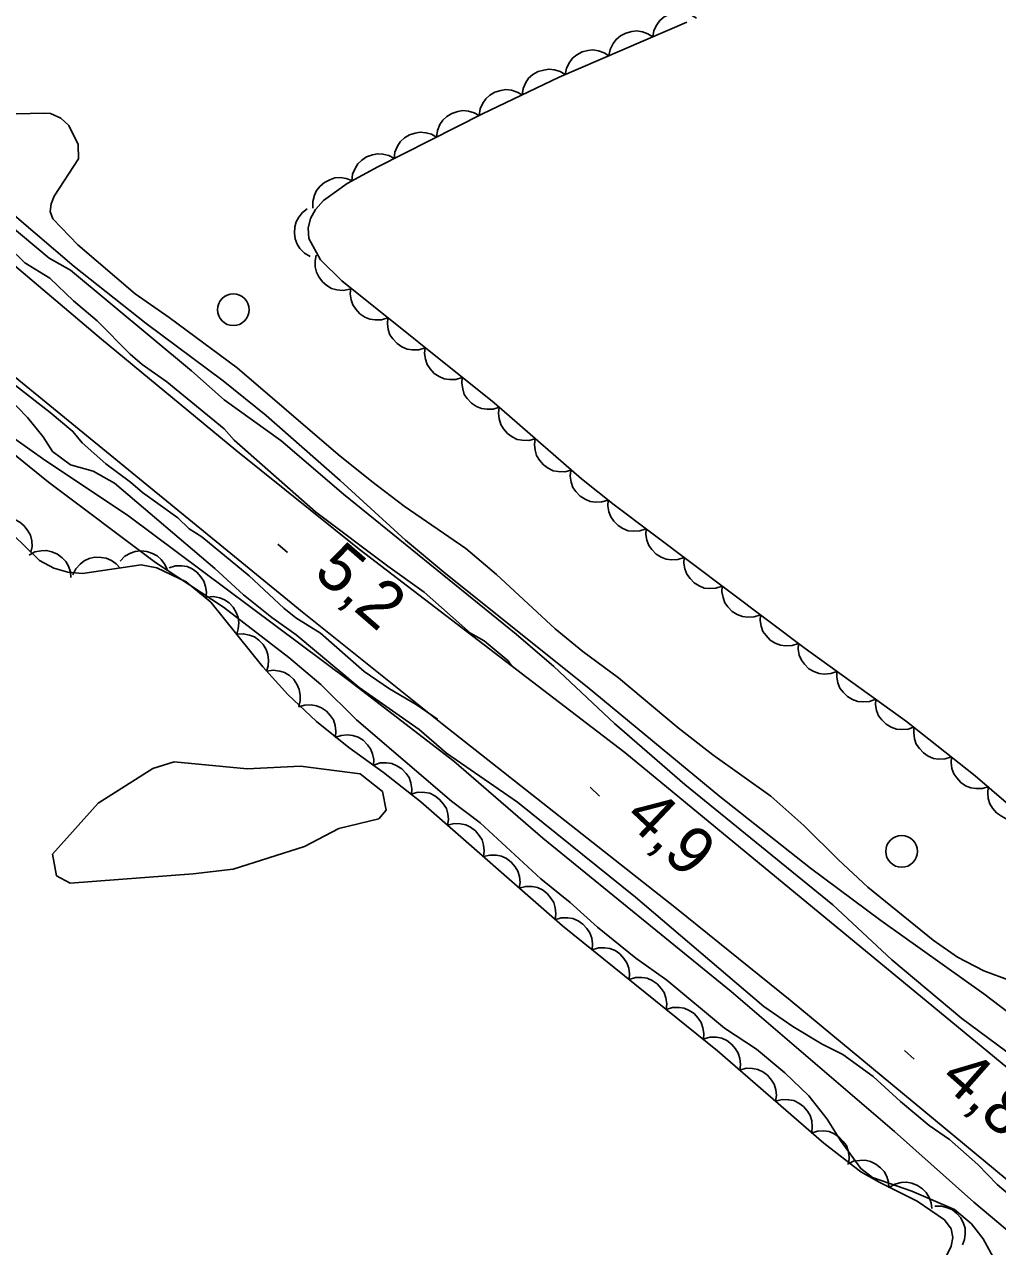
# Model space of a CAD drawing. Extents: x 336540 to 340074, y 5572036 to 5573747.
# Drawn here: x 337589.4 to 337650.7, y 5572818.2 to 5572895.2 of the extents above; entities that cross this region are included whole.
import ezdxf

# ---------------------------------------------------------------- set-up
doc = ezdxf.new("R2010")
doc.units = 0
for name, color, linetype in [('Niveau 1', 7, 'Continuous'), ('Niveau 19', 7, 'Continuous'), ('Niveau 2', 7, 'Continuous'), ('Niveau 3', 7, 'Continuous'), ('Niveau 36', 7, 'Continuous'), ('Niveau 4', 7, 'Continuous'), ('Niveau 44', 7, 'Continuous')]:
    doc.layers.add(name, color=color, linetype=linetype)

msp = doc.modelspace()

# ---------------------------------------------------------------- linework, layer by layer
at = {"layer": 'Niveau 1'}
for points in [[(337586.33, 5572883.16), (337589.41, 5572880.15), (337590.98, 5572879.19), (337592.48, 5572877.76), (337593.97, 5572876.5), (337596.05, 5572874.4), (337596.8, 5572873.74), (337598.35, 5572872.65), (337601.97, 5572869.7), (337602.6, 5572868.98), (337607.72, 5572864.48), (337612.26, 5572861.04), (337614.55, 5572859.4), (337617.48, 5572856.82), (337618.34, 5572856.34), (337619.84, 5572855.08), (337620.08, 5572854.75)], [(337615.4, 5572851.4), (337614.04, 5572852.34), (337612.38, 5572853.32), (337610.78, 5572854.41), (337608.02, 5572856.82), (337606.47, 5572857.8), (337605.72, 5572858.4), (337603.54, 5572860.43), (337600.55, 5572862.9), (337599.75, 5572863.39), (337599.05, 5572864.1), (337596.82, 5572865.68), (337596.07, 5572866.34), (337594.52, 5572867.49), (337593.02, 5572868.81), (337592.44, 5572869.53), (337591.01, 5572870.73), (337588.83, 5572872.43)], [(337600.02, 5572841.67), (337592.27, 5572841.09), (337591.4, 5572841.55), (337591.15, 5572842.9), (337594.03, 5572846.12), (337597.47, 5572848.31), (337598.81, 5572848.72), (337603.41, 5572848.28), (337606.77, 5572848.45), (337610.52, 5572847.96), (337611.92, 5572846.85), (337612.16, 5572845.67), (337611.69, 5572845.14), (337609.18, 5572844.52), (337607.03, 5572843.38), (337602.53, 5572841.96), (337600.02, 5572841.67)]]:
    msp.add_lwpolyline(points, dxfattribs=at)
at = {"layer": 'Niveau 19'}
for points in [[(337747.9, 5572743.42), (337733.2, 5572755.24), (337714.79, 5572770.78), (337697.31, 5572784.55), (337659.54, 5572815.53), (337637.6, 5572833.7), (337630.44, 5572839.48), (337615.68, 5572851.12), (337606.88, 5572858.17), (337562.43, 5572894.51)], [(337585.33, 5572882.89), (337594.24, 5572875.34), (337602.7, 5572868.36), (337610.46, 5572862.12), (337627.18, 5572849.32), (337671.83, 5572812.51), (337696.95, 5572792.34), (337706.42, 5572784.95), (337712.98, 5572779.69), (337742.53, 5572755.28)]]:
    msp.add_lwpolyline(points, dxfattribs=at)
at = {"layer": 'Niveau 2'}
for points in [[(337586.16, 5572889.48), (337590.66, 5572889.59), (337591.03, 5572889.55), (337591.69, 5572889.27), (337592.19, 5572888.81), (337592.78, 5572887.6), (337592.8, 5572886.7), (337591.27, 5572884.36), (337591.07, 5572883.87), (337591, 5572883.38), (337591.17, 5572882.92), (337592.74, 5572881.28), (337596.35, 5572878.21), (337598.5, 5572876.72), (337602.78, 5572873.54), (337609.13, 5572868.08), (337611.25, 5572866.37), (337613.3, 5572864.83), (337617.17, 5572862.16), (337619.1, 5572860.52), (337622.8, 5572857.11), (337624.54, 5572855.67), (337626.78, 5572854.02), (337630.55, 5572850.86), (337632.72, 5572849.16), (337636.38, 5572846.57), (337638.46, 5572844.72), (337640.63, 5572842.54), (337642.48, 5572840.83), (337646.6, 5572837.48), (337648.13, 5572836.42), (337649.79, 5572835.55), (337651.49, 5572834.93)], [(337667.74, 5572817.19), (337666.07, 5572818.77), (337665.04, 5572819.91), (337663.29, 5572821.4), (337661.2, 5572822.91), (337659.35, 5572824.37), (337654.91, 5572827.58), (337652.86, 5572829.25), (337648.4, 5572832.55), (337643.99, 5572836.26), (337640.29, 5572839.72), (337630.97, 5572847.29), (337626.53, 5572851.14), (337622.71, 5572854.73), (337620.34, 5572856.76), (337609.48, 5572865.58), (337605.52, 5572868.96), (337601.96, 5572871.53), (337599.9, 5572873.35), (337592.29, 5572879.69), (337590.94, 5572880.45), (337587.44, 5572883.37)], [(337588.34, 5572871.69), (337589.59, 5572870.41), (337590.57, 5572869.2), (337591.16, 5572868.26), (337592.29, 5572867.44), (337593.71, 5572867.03), (337595.05, 5572866.28), (337601.38, 5572860.9), (337603.17, 5572859.24), (337604.96, 5572857.81), (337606.5, 5572856.73), (337610.47, 5572853.4), (337614.23, 5572850.75), (337615.95, 5572849.27)], [(337650.49, 5572817.29), (337649.74, 5572818.67), (337649, 5572819.62), (337647.94, 5572820.53), (337645.25, 5572821.67), (337642.77, 5572822.53), (337642.04, 5572823.1), (337640.76, 5572824.88), (337639.93, 5572826.21), (337638.76, 5572827.69), (337637.25, 5572829.14), (337635.48, 5572830.63), (337633.46, 5572831.94), (337629.82, 5572834.97), (337627.88, 5572836.35), (337625.47, 5572838.31), (337623.74, 5572839.86), (337621.9, 5572841.36), (337618.08, 5572844.88), (337616.27, 5572846.24), (337610.29, 5572851.36), (337608.04, 5572853.59), (337606.04, 5572855.29), (337601.92, 5572858.47), (337597.63, 5572861.27), (337590.91, 5572866.33), (337586.9, 5572869.57)], [(337615.95, 5572849.27), (337620.42, 5572846.19), (337627.86, 5572840.19), (337635.94, 5572833.31), (337637.76, 5572832.05), (337639.6, 5572830.94), (337640.9, 5572830.28), (337642.81, 5572828.91), (337644.54, 5572827.32), (337646.35, 5572825.82), (337647.62, 5572824.93), (337649.41, 5572823.35), (337650.62, 5572822.1), (337651.89, 5572821.03), (337653.25, 5572820.1), (337655.06, 5572818.59), (337656.92, 5572816.8)]]:
    msp.add_lwpolyline(points, dxfattribs=at)
at = {"layer": 'Niveau 3'}
for p, q in [((337605.35, 5572862.43), (337605.96, 5572861.9)), ((337625, 5572847.12), (337625.59, 5572846.57)), ((337644.79, 5572830.53), (337645.4, 5572830))]:
    msp.add_line(p, q, dxfattribs=at)
at = {"layer": 'Niveau 36'}
for centre in [(337602.539, 5572877.201), (337644.609, 5572843.081)]:
    msp.add_circle(centre, 1, dxfattribs=at)
at = {"layer": 'Niveau 4'}
for points in [[(337581.38, 5572889.43), (337592.52, 5572879.92), (337597.05, 5572876.33), (337601.9, 5572872.72), (337604.6, 5572870.54), (337609.27, 5572866.45), (337613.37, 5572862.68), (337615.91, 5572860.57), (337624.81, 5572853.45), (337633.16, 5572846.53), (337638.87, 5572842.03), (337643.3, 5572838.72), (337649.78, 5572834.11), (337653.45, 5572831.32), (337655.58, 5572829.56), (337666.32, 5572820.01), (337674.23, 5572813.3), (337681.73, 5572807.3), (337686.77, 5572803.82), (337693.83, 5572798.21)], [(337587.92, 5572869.67), (337590.52, 5572867.82), (337595.97, 5572864.2), (337609.79, 5572853.86), (337616.42, 5572848.76), (337622.03, 5572843.92), (337633.87, 5572834.25), (337644.17, 5572825.44), (337649.15, 5572820.98), (337662.3, 5572809.95), (337669.6, 5572804.24), (337675.77, 5572799.23), (337681.99, 5572794.33), (337687.59, 5572790.49), (337697.46, 5572781.61), (337702.07, 5572777.76), (337707.2, 5572774.01), (337712.37, 5572769.72), (337716.28, 5572765.83), (337730.4, 5572754.32), (337734.94, 5572750.56), (337739.53, 5572746.61)]]:
    msp.add_lwpolyline(points, dxfattribs=at)
at = {"layer": 'Niveau 44'}
for points in [[(337628.94, 5572894.38), (337629.02, 5572894.79), (337629.21, 5572895.15), (337629.4, 5572895.42), (337629.67, 5572895.64), (337630, 5572895.81), (337630.37, 5572895.91), (337630.69, 5572895.95), (337631.04, 5572895.89), (337631.39, 5572895.76), (337631.69, 5572895.57)], [(337658.09, 5572840.21), (337649.24, 5572847.85), (337644.92, 5572851.27), (337638.53, 5572855.87), (337626.51, 5572864.92), (337624.45, 5572866.54), (337618.95, 5572871.33), (337609.36, 5572879.01), (337608.03, 5572880.35), (337607.3, 5572881.68), (337607.26, 5572882.33), (337607.39, 5572882.95), (337607.71, 5572883.52), (337608.22, 5572884.08), (337609.71, 5572885.15), (337611.64, 5572886.2), (337618.23, 5572889.54), (337623.05, 5572891.84), (337631.09, 5572895.31)], [(337626.18, 5572893.19), (337626.26, 5572893.6), (337626.45, 5572893.96), (337626.64, 5572894.23), (337626.92, 5572894.45), (337627.24, 5572894.63), (337627.62, 5572894.72), (337627.94, 5572894.76), (337628.29, 5572894.7), (337628.64, 5572894.58), (337628.94, 5572894.38)], [(337623.43, 5572892), (337623.51, 5572892.41), (337623.7, 5572892.77), (337623.89, 5572893.04), (337624.16, 5572893.26), (337624.49, 5572893.44), (337624.86, 5572893.53), (337625.18, 5572893.57), (337625.53, 5572893.51), (337625.88, 5572893.39), (337626.18, 5572893.19)], [(337620.72, 5572890.73), (337620.78, 5572891.14), (337620.95, 5572891.51), (337621.13, 5572891.78), (337621.4, 5572892.01), (337621.72, 5572892.2), (337622.09, 5572892.3), (337622.41, 5572892.36), (337622.76, 5572892.31), (337623.11, 5572892.2), (337623.42, 5572892.02)], [(337618.01, 5572889.43), (337618.07, 5572889.85), (337618.25, 5572890.21), (337618.43, 5572890.49), (337618.69, 5572890.72), (337619.01, 5572890.91), (337619.38, 5572891.01), (337619.7, 5572891.07), (337620.05, 5572891.02), (337620.41, 5572890.91), (337620.72, 5572890.73)], [(337615.34, 5572888.07), (337615.39, 5572888.49), (337615.55, 5572888.86), (337615.73, 5572889.14), (337615.99, 5572889.37), (337616.3, 5572889.57), (337616.67, 5572889.68), (337616.99, 5572889.75), (337617.34, 5572889.71), (337617.7, 5572889.6), (337618.01, 5572889.43)], [(337612.66, 5572886.72), (337612.71, 5572887.13), (337612.88, 5572887.5), (337613.05, 5572887.78), (337613.31, 5572888.02), (337613.63, 5572888.21), (337613.99, 5572888.33), (337614.31, 5572888.39), (337614.66, 5572888.35), (337615.02, 5572888.25), (337615.34, 5572888.07)], [(337610.01, 5572885.31), (337610.05, 5572885.73), (337610.2, 5572886.1), (337610.37, 5572886.39), (337610.63, 5572886.63), (337610.93, 5572886.84), (337611.3, 5572886.96), (337611.61, 5572887.03), (337611.96, 5572887), (337612.32, 5572886.91), (337612.64, 5572886.75)], [(337607.55, 5572883.6), (337607.54, 5572884.02), (337607.65, 5572884.41), (337607.77, 5572884.71), (337608, 5572884.98), (337608.28, 5572885.22), (337608.62, 5572885.39), (337608.93, 5572885.5), (337609.28, 5572885.52), (337609.65, 5572885.47), (337609.99, 5572885.35)], [(337607.37, 5572880.55), (337607.01, 5572880.76), (337606.73, 5572881.06), (337606.55, 5572881.34), (337606.44, 5572881.67), (337606.38, 5572882.03), (337606.42, 5572882.42), (337606.49, 5572882.73), (337606.67, 5572883.04), (337606.9, 5572883.33), (337607.19, 5572883.55)], [(337609.87, 5572878.5), (337609.46, 5572878.42), (337609.06, 5572878.46), (337608.73, 5572878.54), (337608.43, 5572878.72), (337608.15, 5572878.96), (337607.93, 5572879.27), (337607.77, 5572879.56), (337607.7, 5572879.9), (337607.69, 5572880.27), (337607.76, 5572880.63)], [(337612.27, 5572876.68), (337611.87, 5572876.56), (337611.46, 5572876.56), (337611.13, 5572876.6), (337610.81, 5572876.74), (337610.5, 5572876.95), (337610.25, 5572877.23), (337610.06, 5572877.5), (337609.95, 5572877.83), (337609.9, 5572878.2), (337609.93, 5572878.56)], [(337614.61, 5572874.81), (337614.21, 5572874.68), (337613.8, 5572874.68), (337613.48, 5572874.72), (337613.15, 5572874.86), (337612.85, 5572875.07), (337612.59, 5572875.36), (337612.4, 5572875.62), (337612.29, 5572875.96), (337612.24, 5572876.32), (337612.27, 5572876.68)], [(337616.95, 5572872.93), (337616.55, 5572872.81), (337616.14, 5572872.81), (337615.82, 5572872.85), (337615.5, 5572872.99), (337615.19, 5572873.19), (337614.93, 5572873.48), (337614.74, 5572873.75), (337614.63, 5572874.08), (337614.58, 5572874.45), (337614.61, 5572874.81)], [(337619.29, 5572871.06), (337618.89, 5572870.93), (337618.49, 5572870.93), (337618.16, 5572870.97), (337617.84, 5572871.11), (337617.53, 5572871.32), (337617.27, 5572871.61), (337617.08, 5572871.87), (337616.98, 5572872.21), (337616.92, 5572872.57), (337616.95, 5572872.93)], [(337621.54, 5572869.07), (337621.14, 5572868.96), (337620.73, 5572868.98), (337620.41, 5572869.03), (337620.09, 5572869.19), (337619.79, 5572869.41), (337619.55, 5572869.7), (337619.37, 5572869.98), (337619.28, 5572870.32), (337619.24, 5572870.68), (337619.28, 5572871.04)], [(337623.81, 5572867.1), (337623.4, 5572866.99), (337622.99, 5572867.01), (337622.67, 5572867.06), (337622.35, 5572867.22), (337622.06, 5572867.44), (337621.81, 5572867.73), (337621.63, 5572868.01), (337621.54, 5572868.35), (337621.5, 5572868.71), (337621.54, 5572869.07)], [(337626.14, 5572865.21), (337625.74, 5572865.09), (337625.33, 5572865.08), (337625, 5572865.12), (337624.68, 5572865.26), (337624.37, 5572865.46), (337624.11, 5572865.75), (337623.92, 5572866.01), (337623.81, 5572866.34), (337623.75, 5572866.71), (337623.78, 5572867.07)], [(337628.53, 5572863.4), (337628.13, 5572863.27), (337627.72, 5572863.25), (337627.4, 5572863.28), (337627.07, 5572863.42), (337626.76, 5572863.61), (337626.49, 5572863.89), (337626.3, 5572864.15), (337626.18, 5572864.48), (337626.11, 5572864.85), (337626.13, 5572865.21)], [(337587.65, 5572864.01), (337588.06, 5572864.1), (337588.46, 5572864.06), (337588.79, 5572863.99), (337589.09, 5572863.81), (337589.38, 5572863.58), (337589.61, 5572863.27), (337589.77, 5572862.99), (337589.85, 5572862.65), (337589.87, 5572862.28), (337589.8, 5572861.92)], [(337630.92, 5572861.6), (337630.53, 5572861.46), (337630.12, 5572861.45), (337629.79, 5572861.48), (337629.47, 5572861.61), (337629.15, 5572861.81), (337628.89, 5572862.09), (337628.69, 5572862.35), (337628.57, 5572862.68), (337628.51, 5572863.04), (337628.53, 5572863.4)], [(337588.65, 5572863.04), (337590.34, 5572861.4), (337591.23, 5572860.92), (337592.13, 5572860.66), (337593.05, 5572860.59), (337596.74, 5572861.13), (337597.72, 5572860.95), (337599.57, 5572860.06), (337601.13, 5572858.77), (337604.4, 5572854.7), (337605.98, 5572852.96), (337607.78, 5572851.26), (337609.81, 5572849.62), (337612, 5572848.04), (337614.35, 5572846.2), (337623.26, 5572838.39), (337633.02, 5572830.52), (337639.72, 5572824.71), (337642.05, 5572822.89), (337643.23, 5572822.22), (337645.59, 5572821.05), (337647.32, 5572819.87), (337647.72, 5572819.31), (337647.83, 5572818.77), (337647.74, 5572818.22), (337646.85, 5572816.39)], [(337589.68, 5572861.75), (337590.05, 5572861.95), (337590.45, 5572862.02), (337590.78, 5572862.04), (337591.12, 5572861.96), (337591.46, 5572861.81), (337591.77, 5572861.58), (337592, 5572861.35), (337592.17, 5572861.04), (337592.29, 5572860.69), (337592.32, 5572860.33)], [(337595.41, 5572861.37), (337595.71, 5572861.67), (337596.06, 5572861.87), (337596.37, 5572861.98), (337596.72, 5572862.01), (337597.09, 5572861.98), (337597.45, 5572861.85), (337597.74, 5572861.7), (337598, 5572861.46), (337598.22, 5572861.16), (337598.37, 5572860.83)], [(337592.44, 5572860.5), (337592.62, 5572860.88), (337592.9, 5572861.18), (337593.15, 5572861.39), (337593.47, 5572861.53), (337593.83, 5572861.61), (337594.22, 5572861.6), (337594.54, 5572861.56), (337594.86, 5572861.41), (337595.16, 5572861.2), (337595.41, 5572860.93)], [(337598.49, 5572860.95), (337598.89, 5572861.07), (337599.3, 5572861.06), (337599.63, 5572861.02), (337599.95, 5572860.87), (337600.25, 5572860.66), (337600.5, 5572860.37), (337600.69, 5572860.1), (337600.79, 5572859.76), (337600.84, 5572859.4), (337600.81, 5572859.04)], [(337633.32, 5572859.79), (337632.92, 5572859.66), (337632.52, 5572859.64), (337632.19, 5572859.67), (337631.86, 5572859.81), (337631.55, 5572860), (337631.29, 5572860.28), (337631.09, 5572860.54), (337630.97, 5572860.87), (337630.91, 5572861.24), (337630.92, 5572861.6)], [(337635.72, 5572857.99), (337635.32, 5572857.85), (337634.91, 5572857.84), (337634.59, 5572857.87), (337634.26, 5572858), (337633.95, 5572858.2), (337633.68, 5572858.48), (337633.49, 5572858.74), (337633.37, 5572859.07), (337633.3, 5572859.43), (337633.32, 5572859.79)], [(337600.87, 5572859.1), (337601.28, 5572859.13), (337601.68, 5572859.05), (337601.99, 5572858.93), (337602.27, 5572858.73), (337602.53, 5572858.46), (337602.72, 5572858.12), (337602.84, 5572857.82), (337602.88, 5572857.47), (337602.85, 5572857.1), (337602.75, 5572856.76)], [(337638.11, 5572856.18), (337637.72, 5572856.05), (337637.31, 5572856.03), (337636.98, 5572856.07), (337636.66, 5572856.2), (337636.34, 5572856.39), (337636.08, 5572856.67), (337635.88, 5572856.93), (337635.76, 5572857.26), (337635.7, 5572857.63), (337635.72, 5572857.99)], [(337602.75, 5572856.76), (337603.16, 5572856.79), (337603.56, 5572856.71), (337603.87, 5572856.6), (337604.15, 5572856.39), (337604.41, 5572856.12), (337604.6, 5572855.79), (337604.72, 5572855.49), (337604.76, 5572855.13), (337604.73, 5572854.77), (337604.62, 5572854.42)], [(337640.54, 5572854.42), (337640.15, 5572854.28), (337639.74, 5572854.25), (337639.41, 5572854.28), (337639.09, 5572854.41), (337638.77, 5572854.59), (337638.5, 5572854.87), (337638.3, 5572855.12), (337638.17, 5572855.45), (337638.1, 5572855.82), (337638.11, 5572856.17)], [(337604.64, 5572854.43), (337605.05, 5572854.49), (337605.46, 5572854.43), (337605.77, 5572854.34), (337606.07, 5572854.15), (337606.34, 5572853.9), (337606.55, 5572853.57), (337606.69, 5572853.28), (337606.75, 5572852.93), (337606.74, 5572852.56), (337606.66, 5572852.21)], [(337642.98, 5572852.67), (337642.58, 5572852.53), (337642.18, 5572852.5), (337641.85, 5572852.53), (337641.52, 5572852.65), (337641.2, 5572852.84), (337640.93, 5572853.11), (337640.73, 5572853.37), (337640.6, 5572853.7), (337640.53, 5572854.06), (337640.54, 5572854.42)], [(337645.41, 5572850.92), (337645.02, 5572850.77), (337644.61, 5572850.75), (337644.28, 5572850.77), (337643.95, 5572850.9), (337643.64, 5572851.09), (337643.37, 5572851.36), (337643.16, 5572851.62), (337643.04, 5572851.95), (337642.97, 5572852.31), (337642.98, 5572852.67)], [(337606.64, 5572852.18), (337607.04, 5572852.3), (337607.44, 5572852.31), (337607.77, 5572852.26), (337608.09, 5572852.12), (337608.4, 5572851.91), (337608.65, 5572851.62), (337608.84, 5572851.36), (337608.95, 5572851.02), (337609, 5572850.66), (337608.97, 5572850.3)], [(337647.75, 5572849.03), (337647.35, 5572848.91), (337646.94, 5572848.9), (337646.61, 5572848.94), (337646.29, 5572849.08), (337645.98, 5572849.29), (337645.73, 5572849.57), (337645.53, 5572849.83), (337645.42, 5572850.17), (337645.37, 5572850.54), (337645.39, 5572850.89)], [(337608.94, 5572850.25), (337609.33, 5572850.39), (337609.73, 5572850.42), (337610.06, 5572850.39), (337610.39, 5572850.27), (337610.71, 5572850.08), (337610.98, 5572849.8), (337611.18, 5572849.55), (337611.31, 5572849.22), (337611.38, 5572848.86), (337611.37, 5572848.5)], [(337611.39, 5572848.52), (337611.78, 5572848.65), (337612.19, 5572848.65), (337612.52, 5572848.62), (337612.84, 5572848.48), (337613.15, 5572848.28), (337613.41, 5572847.99), (337613.6, 5572847.73), (337613.72, 5572847.4), (337613.77, 5572847.03), (337613.75, 5572846.67)], [(337650.1, 5572847.17), (337649.7, 5572847.04), (337649.29, 5572847.04), (337648.97, 5572847.08), (337648.64, 5572847.22), (337648.33, 5572847.42), (337648.08, 5572847.71), (337647.89, 5572847.97), (337647.78, 5572848.31), (337647.72, 5572848.67), (337647.75, 5572849.03)], [(337652.34, 5572845.17), (337651.94, 5572845.07), (337651.53, 5572845.08), (337651.2, 5572845.13), (337650.89, 5572845.29), (337650.59, 5572845.5), (337650.34, 5572845.8), (337650.16, 5572846.07), (337650.07, 5572846.41), (337650.03, 5572846.78), (337650.07, 5572847.13)], [(337613.78, 5572846.7), (337614.18, 5572846.81), (337614.59, 5572846.79), (337614.91, 5572846.74), (337615.23, 5572846.58), (337615.52, 5572846.36), (337615.77, 5572846.06), (337615.95, 5572845.79), (337616.04, 5572845.45), (337616.08, 5572845.08), (337616.03, 5572844.73)], [(337616.03, 5572844.73), (337616.44, 5572844.83), (337616.84, 5572844.82), (337617.17, 5572844.76), (337617.48, 5572844.6), (337617.78, 5572844.38), (337618.02, 5572844.09), (337618.2, 5572843.81), (337618.29, 5572843.47), (337618.33, 5572843.11), (337618.29, 5572842.75)], [(337618.29, 5572842.75), (337618.69, 5572842.85), (337619.1, 5572842.84), (337619.42, 5572842.78), (337619.74, 5572842.63), (337620.04, 5572842.41), (337620.28, 5572842.11), (337620.46, 5572841.84), (337620.55, 5572841.5), (337620.59, 5572841.13), (337620.54, 5572840.77)], [(337620.54, 5572840.77), (337620.95, 5572840.88), (337621.35, 5572840.86), (337621.68, 5572840.8), (337622, 5572840.65), (337622.29, 5572840.43), (337622.53, 5572840.13), (337622.71, 5572839.86), (337622.81, 5572839.52), (337622.84, 5572839.15), (337622.8, 5572838.79)], [(337622.78, 5572838.77), (337623.18, 5572838.9), (337623.59, 5572838.9), (337623.92, 5572838.85), (337624.24, 5572838.71), (337624.55, 5572838.5), (337624.8, 5572838.22), (337624.99, 5572837.95), (337625.1, 5572837.62), (337625.15, 5572837.25), (337625.12, 5572836.89)], [(337625.12, 5572836.89), (337625.52, 5572837.01), (337625.93, 5572837.01), (337626.25, 5572836.97), (337626.57, 5572836.83), (337626.88, 5572836.62), (337627.13, 5572836.33), (337627.32, 5572836.07), (337627.43, 5572835.73), (337627.48, 5572835.37), (337627.45, 5572835.01)], [(337627.45, 5572835.01), (337627.85, 5572835.13), (337628.26, 5572835.13), (337628.59, 5572835.09), (337628.91, 5572834.94), (337629.22, 5572834.74), (337629.47, 5572834.45), (337629.66, 5572834.19), (337629.77, 5572833.85), (337629.82, 5572833.48), (337629.79, 5572833.12)], [(337629.79, 5572833.12), (337630.19, 5572833.25), (337630.6, 5572833.25), (337630.92, 5572833.2), (337631.24, 5572833.06), (337631.55, 5572832.86), (337631.81, 5572832.57), (337631.99, 5572832.3), (337632.1, 5572831.97), (337632.16, 5572831.6), (337632.13, 5572831.24)], [(337632.15, 5572831.27), (337632.56, 5572831.38), (337632.96, 5572831.37), (337633.29, 5572831.31), (337633.6, 5572831.16), (337633.9, 5572830.94), (337634.15, 5572830.64), (337634.33, 5572830.37), (337634.42, 5572830.03), (337634.46, 5572829.66), (337634.42, 5572829.31)], [(337634.42, 5572829.31), (337634.82, 5572829.42), (337635.23, 5572829.4), (337635.55, 5572829.35), (337635.87, 5572829.19), (337636.17, 5572828.98), (337636.41, 5572828.68), (337636.59, 5572828.41), (337636.69, 5572828.07), (337636.73, 5572827.7), (337636.68, 5572827.34)], [(337636.68, 5572827.34), (337637.09, 5572827.45), (337637.49, 5572827.44), (337637.82, 5572827.38), (337638.14, 5572827.23), (337638.44, 5572827.01), (337638.68, 5572826.71), (337638.86, 5572826.44), (337638.95, 5572826.1), (337638.99, 5572825.73), (337638.95, 5572825.38)], [(337638.92, 5572825.34), (337639.32, 5572825.46), (337639.72, 5572825.47), (337640.05, 5572825.43), (337640.37, 5572825.3), (337640.68, 5572825.09), (337640.94, 5572824.81), (337641.14, 5572824.55), (337641.25, 5572824.21), (337641.31, 5572823.85), (337641.28, 5572823.49)], [(337641.2, 5572823.37), (337641.58, 5572823.56), (337641.98, 5572823.62), (337642.31, 5572823.63), (337642.65, 5572823.54), (337642.98, 5572823.39), (337643.28, 5572823.15), (337643.51, 5572822.92), (337643.67, 5572822.6), (337643.78, 5572822.25), (337643.81, 5572821.89)], [(337643.83, 5572821.92), (337644.19, 5572822.13), (337644.59, 5572822.22), (337644.92, 5572822.25), (337645.26, 5572822.18), (337645.61, 5572822.04), (337645.92, 5572821.82), (337646.16, 5572821.6), (337646.34, 5572821.29), (337646.47, 5572820.95), (337646.52, 5572820.59)], [(337646.7, 5572820.73), (337647.12, 5572820.74), (337647.51, 5572820.63), (337647.82, 5572820.5), (337648.09, 5572820.28), (337648.33, 5572820), (337648.5, 5572819.65), (337648.61, 5572819.35), (337648.62, 5572819), (337648.57, 5572818.63), (337648.45, 5572818.29)]]:
    msp.add_lwpolyline(points, dxfattribs=at)

# ---------------------------------------------------------------- texts
at = {"layer": 'Niveau 3'}
for s, rotation, p in [('5,2    ', 319.07177, (337607.5, 5572860.51)), ('4,9    ', 316.59498, (337627.06, 5572845.12)), ('4,8    ', 318.57585, (337646.92, 5572828.6))]:
    msp.add_text(s, height=2.9999, rotation=rotation, dxfattribs=at).set_placement(p)

doc.saveas('drawing.dxf')
